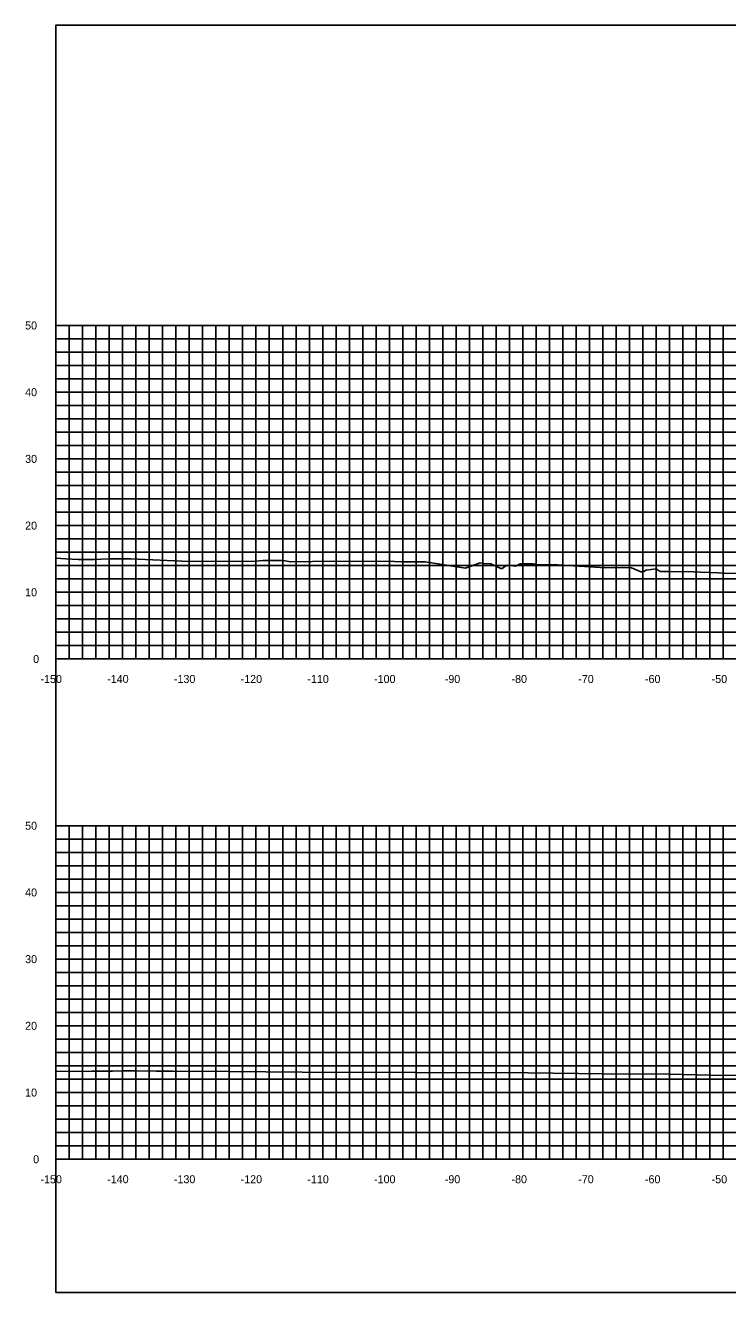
# Model space of a CAD drawing. Extents: x 1797714 to 1804825, y 249015 to 250269.
# Drawn here: x 1802109.6 to 1802214.9, y 249628.2 to 249818.2 of the extents above; entities that cross this region are included whole.
import ezdxf

# ---------------------------------------------------------------- set-up
doc = ezdxf.new("R2010")
doc.units = 0
for name, color, linetype in [('10', 7, 'Continuous'), ('31', 7, 'Continuous'), ('60', 7, 'Continuous'), ('Level 62', 7, 'Continuous'), ('M-ROADS', 7, 'Continuous')]:
    doc.layers.add(name, color=color, linetype=linetype)

msp = doc.modelspace()

# ---------------------------------------------------------------- linework, layer by layer
msp.add_lwpolyline([(1802114.16, 249628.17), (1802414.16, 249628.17), (1802414.16, 249818.17), (1802114.16, 249818.17)], close=True)
at = {"layer": '60'}
for p, q in [((1802114.1, 249773.17), (1802114.16, 249773.17)), ((1802114.16, 249723.17), (1802114.16, 249773.17)), ((1802114.1, 249763.17), (1802114.16, 249763.17)), ((1802114.1, 249753.17), (1802114.16, 249753.17)), ((1802114.1, 249743.17), (1802114.16, 249743.17)), ((1802114.1, 249733.17), (1802114.16, 249733.17)), ((1802114.1, 249723.17), (1802114.16, 249723.17)), ((1802114.16, 249723.17), (1802414.16, 249723.17)), ((1802114.16, 249723.11), (1802114.16, 249723.17)), ((1802124.16, 249723.11), (1802124.16, 249723.17)), ((1802134.16, 249723.11), (1802134.16, 249723.17)), ((1802144.16, 249723.11), (1802144.16, 249723.17)), ((1802154.16, 249723.11), (1802154.16, 249723.17)), ((1802164.16, 249723.11), (1802164.16, 249723.17)), ((1802174.16, 249723.11), (1802174.16, 249723.17)), ((1802184.16, 249723.11), (1802184.16, 249723.17)), ((1802194.16, 249723.11), (1802194.16, 249723.17)), ((1802204.16, 249723.11), (1802204.16, 249723.17)), ((1802214.16, 249723.11), (1802214.16, 249723.17)), ((1802114.1, 249698.17), (1802114.16, 249698.17)), ((1802114.16, 249648.17), (1802114.16, 249698.17)), ((1802114.1, 249688.17), (1802114.16, 249688.17)), ((1802114.1, 249678.17), (1802114.16, 249678.17)), ((1802114.1, 249668.17), (1802114.16, 249668.17)), ((1802114.1, 249658.17), (1802114.16, 249658.17)), ((1802114.1, 249648.17), (1802114.16, 249648.17)), ((1802114.16, 249648.17), (1802414.16, 249648.17)), ((1802114.16, 249648.11), (1802114.16, 249648.17)), ((1802124.16, 249648.11), (1802124.16, 249648.17)), ((1802134.16, 249648.11), (1802134.16, 249648.17)), ((1802144.16, 249648.11), (1802144.16, 249648.17)), ((1802154.16, 249648.11), (1802154.16, 249648.17)), ((1802164.16, 249648.11), (1802164.16, 249648.17)), ((1802174.16, 249648.11), (1802174.16, 249648.17)), ((1802184.16, 249648.11), (1802184.16, 249648.17)), ((1802194.16, 249648.11), (1802194.16, 249648.17)), ((1802204.16, 249648.11), (1802204.16, 249648.17)), ((1802214.16, 249648.11), (1802214.16, 249648.17))]:
    msp.add_line(p, q, dxfattribs=at)
at = {"layer": 'Level 62'}
for p, q in [((1802114.16, 249773.17), (1802414.16, 249773.17)), ((1802114.16, 249723.17), (1802114.16, 249773.17)), ((1802116.16, 249723.17), (1802116.16, 249773.17)), ((1802118.16, 249723.17), (1802118.16, 249773.17)), ((1802120.16, 249723.17), (1802120.16, 249773.17)), ((1802122.16, 249723.17), (1802122.16, 249773.17)), ((1802124.16, 249723.17), (1802124.16, 249773.17)), ((1802126.16, 249723.17), (1802126.16, 249773.17)), ((1802128.16, 249723.17), (1802128.16, 249773.17)), ((1802130.16, 249723.17), (1802130.16, 249773.17)), ((1802132.16, 249723.17), (1802132.16, 249773.17)), ((1802134.16, 249723.17), (1802134.16, 249773.17)), ((1802136.16, 249723.17), (1802136.16, 249773.17)), ((1802138.16, 249723.17), (1802138.16, 249773.17)), ((1802140.16, 249723.17), (1802140.16, 249773.17)), ((1802142.16, 249723.17), (1802142.16, 249773.17)), ((1802144.16, 249723.17), (1802144.16, 249773.17)), ((1802146.16, 249723.17), (1802146.16, 249773.17)), ((1802148.16, 249723.17), (1802148.16, 249773.17)), ((1802150.16, 249723.17), (1802150.16, 249773.17)), ((1802152.16, 249723.17), (1802152.16, 249773.17)), ((1802154.16, 249723.17), (1802154.16, 249773.17)), ((1802156.16, 249723.17), (1802156.16, 249773.17)), ((1802158.16, 249723.17), (1802158.16, 249773.17)), ((1802160.16, 249723.17), (1802160.16, 249773.17)), ((1802162.16, 249723.17), (1802162.16, 249773.17)), ((1802164.16, 249723.17), (1802164.16, 249773.17)), ((1802166.16, 249723.17), (1802166.16, 249773.17)), ((1802168.16, 249723.17), (1802168.16, 249773.17)), ((1802170.16, 249723.17), (1802170.16, 249773.17)), ((1802172.16, 249723.17), (1802172.16, 249773.17)), ((1802174.16, 249723.17), (1802174.16, 249773.17)), ((1802176.16, 249723.17), (1802176.16, 249773.17)), ((1802178.16, 249723.17), (1802178.16, 249773.17)), ((1802180.16, 249723.17), (1802180.16, 249773.17)), ((1802182.16, 249723.17), (1802182.16, 249773.17)), ((1802184.16, 249723.17), (1802184.16, 249773.17)), ((1802186.16, 249723.17), (1802186.16, 249773.17)), ((1802188.16, 249723.17), (1802188.16, 249773.17)), ((1802190.16, 249723.17), (1802190.16, 249773.17)), ((1802192.16, 249723.17), (1802192.16, 249773.17)), ((1802194.16, 249723.17), (1802194.16, 249773.17)), ((1802196.16, 249723.17), (1802196.16, 249773.17)), ((1802198.16, 249723.17), (1802198.16, 249773.17)), ((1802200.16, 249723.17), (1802200.16, 249773.17)), ((1802202.16, 249723.17), (1802202.16, 249773.17)), ((1802204.16, 249723.17), (1802204.16, 249773.17)), ((1802206.16, 249723.17), (1802206.16, 249773.17)), ((1802208.16, 249723.17), (1802208.16, 249773.17)), ((1802210.16, 249723.17), (1802210.16, 249773.17)), ((1802212.16, 249723.17), (1802212.16, 249773.17)), ((1802214.16, 249723.17), (1802214.16, 249773.17)), ((1802114.16, 249771.17), (1802414.16, 249771.17)), ((1802114.16, 249769.17), (1802414.16, 249769.17)), ((1802114.16, 249767.17), (1802414.16, 249767.17)), ((1802114.16, 249765.17), (1802414.16, 249765.17)), ((1802114.16, 249763.17), (1802414.16, 249763.17)), ((1802114.16, 249761.17), (1802414.16, 249761.17)), ((1802114.16, 249759.17), (1802414.16, 249759.17)), ((1802114.16, 249757.17), (1802414.16, 249757.17)), ((1802114.16, 249755.17), (1802414.16, 249755.17)), ((1802114.16, 249753.17), (1802414.16, 249753.17)), ((1802114.16, 249751.17), (1802414.16, 249751.17)), ((1802114.16, 249749.17), (1802414.16, 249749.17)), ((1802114.16, 249747.17), (1802414.16, 249747.17)), ((1802114.16, 249745.17), (1802414.16, 249745.17)), ((1802114.16, 249743.17), (1802414.16, 249743.17)), ((1802114.16, 249741.17), (1802414.16, 249741.17)), ((1802114.16, 249739.17), (1802414.16, 249739.17)), ((1802114.16, 249737.17), (1802414.16, 249737.17)), ((1802114.16, 249735.17), (1802414.16, 249735.17)), ((1802114.16, 249733.17), (1802414.16, 249733.17)), ((1802114.16, 249731.17), (1802414.16, 249731.17)), ((1802114.16, 249729.17), (1802414.16, 249729.17)), ((1802114.16, 249727.17), (1802414.16, 249727.17)), ((1802114.16, 249725.17), (1802414.16, 249725.17)), ((1802114.16, 249723.17), (1802414.16, 249723.17)), ((1802114.16, 249698.17), (1802414.16, 249698.17)), ((1802114.16, 249648.17), (1802114.16, 249698.17)), ((1802116.16, 249648.17), (1802116.16, 249698.17)), ((1802118.16, 249648.17), (1802118.16, 249698.17)), ((1802120.16, 249648.17), (1802120.16, 249698.17)), ((1802122.16, 249648.17), (1802122.16, 249698.17)), ((1802124.16, 249648.17), (1802124.16, 249698.17)), ((1802126.16, 249648.17), (1802126.16, 249698.17)), ((1802128.16, 249648.17), (1802128.16, 249698.17)), ((1802130.16, 249648.17), (1802130.16, 249698.17)), ((1802132.16, 249648.17), (1802132.16, 249698.17)), ((1802134.16, 249648.17), (1802134.16, 249698.17)), ((1802136.16, 249648.17), (1802136.16, 249698.17)), ((1802138.16, 249648.17), (1802138.16, 249698.17)), ((1802140.16, 249648.17), (1802140.16, 249698.17)), ((1802142.16, 249648.17), (1802142.16, 249698.17)), ((1802144.16, 249648.17), (1802144.16, 249698.17)), ((1802146.16, 249648.17), (1802146.16, 249698.17)), ((1802148.16, 249648.17), (1802148.16, 249698.17)), ((1802150.16, 249648.17), (1802150.16, 249698.17)), ((1802152.16, 249648.17), (1802152.16, 249698.17)), ((1802154.16, 249648.17), (1802154.16, 249698.17)), ((1802156.16, 249648.17), (1802156.16, 249698.17)), ((1802158.16, 249648.17), (1802158.16, 249698.17)), ((1802160.16, 249648.17), (1802160.16, 249698.17)), ((1802162.16, 249648.17), (1802162.16, 249698.17)), ((1802164.16, 249648.17), (1802164.16, 249698.17)), ((1802166.16, 249648.17), (1802166.16, 249698.17)), ((1802168.16, 249648.17), (1802168.16, 249698.17)), ((1802170.16, 249648.17), (1802170.16, 249698.17)), ((1802172.16, 249648.17), (1802172.16, 249698.17)), ((1802174.16, 249648.17), (1802174.16, 249698.17)), ((1802176.16, 249648.17), (1802176.16, 249698.17)), ((1802178.16, 249648.17), (1802178.16, 249698.17)), ((1802180.16, 249648.17), (1802180.16, 249698.17)), ((1802182.16, 249648.17), (1802182.16, 249698.17)), ((1802184.16, 249648.17), (1802184.16, 249698.17)), ((1802186.16, 249648.17), (1802186.16, 249698.17)), ((1802188.16, 249648.17), (1802188.16, 249698.17)), ((1802190.16, 249648.17), (1802190.16, 249698.17)), ((1802192.16, 249648.17), (1802192.16, 249698.17)), ((1802194.16, 249648.17), (1802194.16, 249698.17)), ((1802196.16, 249648.17), (1802196.16, 249698.17)), ((1802198.16, 249648.17), (1802198.16, 249698.17)), ((1802200.16, 249648.17), (1802200.16, 249698.17)), ((1802202.16, 249648.17), (1802202.16, 249698.17)), ((1802204.16, 249648.17), (1802204.16, 249698.17)), ((1802206.16, 249648.17), (1802206.16, 249698.17)), ((1802208.16, 249648.17), (1802208.16, 249698.17)), ((1802210.16, 249648.17), (1802210.16, 249698.17)), ((1802212.16, 249648.17), (1802212.16, 249698.17)), ((1802214.16, 249648.17), (1802214.16, 249698.17)), ((1802114.16, 249696.17), (1802414.16, 249696.17)), ((1802114.16, 249694.17), (1802414.16, 249694.17)), ((1802114.16, 249692.17), (1802414.16, 249692.17)), ((1802114.16, 249690.17), (1802414.16, 249690.17)), ((1802114.16, 249688.17), (1802414.16, 249688.17)), ((1802114.16, 249686.17), (1802414.16, 249686.17)), ((1802114.16, 249684.17), (1802414.16, 249684.17)), ((1802114.16, 249682.17), (1802414.16, 249682.17)), ((1802114.16, 249680.17), (1802414.16, 249680.17)), ((1802114.16, 249678.17), (1802414.16, 249678.17)), ((1802114.16, 249676.17), (1802414.16, 249676.17)), ((1802114.16, 249674.17), (1802414.16, 249674.17)), ((1802114.16, 249672.17), (1802414.16, 249672.17)), ((1802114.16, 249670.17), (1802414.16, 249670.17)), ((1802114.16, 249668.17), (1802414.16, 249668.17)), ((1802114.16, 249666.17), (1802414.16, 249666.17)), ((1802114.16, 249664.17), (1802414.16, 249664.17)), ((1802114.16, 249662.17), (1802414.16, 249662.17)), ((1802114.16, 249660.17), (1802414.16, 249660.17)), ((1802114.16, 249658.17), (1802414.16, 249658.17)), ((1802114.16, 249656.17), (1802414.16, 249656.17)), ((1802114.16, 249654.17), (1802414.16, 249654.17)), ((1802114.16, 249652.17), (1802414.16, 249652.17)), ((1802114.16, 249650.17), (1802414.16, 249650.17)), ((1802114.16, 249648.17), (1802414.16, 249648.17))]:
    msp.add_line(p, q, dxfattribs=at)
at = {"layer": 'M-ROADS'}
for points in [[(1802114.16, 249738.28), (1802115.64, 249738.19), (1802117.53, 249738.08), (1802119.91, 249738.08), (1802122.14, 249738.17), (1802125.39, 249738.2), (1802134.16, 249737.78), (1802144.05, 249737.84), (1802145.19, 249737.94), (1802146.92, 249737.94), (1802148.22, 249737.94), (1802149.37, 249737.71), (1802155.85, 249737.85), (1802164.91, 249737.76), (1802165.98, 249737.74), (1802166.87, 249737.74), (1802168.07, 249737.74), (1802169.51, 249737.75), (1802175.56, 249736.79), (1802175.68, 249736.82), (1802177.74, 249737.58), (1802178.3, 249737.5), (1802179.34, 249737.45), (1802180.87, 249736.75), (1802181.11, 249736.72), (1802181.18, 249736.83), (1802181.81, 249737.22), (1802183.07, 249737.08), (1802183.75, 249737.45), (1802183.79, 249737.44), (1802183.94, 249737.45), (1802185.71, 249737.42), (1802186.53, 249737.28), (1802189.01, 249737.28), (1802189.08, 249737.28), (1802189.33, 249737.27), (1802196.61, 249736.82), (1802199.03, 249736.89), (1802200.42, 249736.82), (1802201.85, 249736.23), (1802202.18, 249736.22), (1802202.62, 249736.49), (1802204.13, 249736.67), (1802204.76, 249736.28), (1802206.11, 249736.3), (1802209.76, 249736.26), (1802210.76, 249736.2), (1802213.46, 249736.08), (1802214.35, 249736.06), (1802216.33, 249736.01)], [(1802114.16, 249661.34), (1802119.55, 249661.35), (1802122.67, 249661.37), (1802124.18, 249661.42), (1802125.6, 249661.41), (1802126.01, 249661.42), (1802126.16, 249661.41), (1802126.22, 249661.41), (1802129.25, 249661.39), (1802131.72, 249661.39), (1802140.2, 249661.34), (1802151.06, 249661.22), (1802184.94, 249661.11), (1802196.27, 249660.97), (1802200.84, 249660.92), (1802204.19, 249660.95), (1802212.33, 249660.77), (1802216.44, 249660.72)]]:
    msp.add_lwpolyline(points, dxfattribs=at)

# ---------------------------------------------------------------- texts
at = {"layer": '10'}
for s, p in [('-150', (1802111.86, 249719.57)), ('-140', (1802121.86, 249719.57)), ('-130', (1802131.86, 249719.57)), ('-120', (1802141.86, 249719.57)), ('-110', (1802151.86, 249719.57)), ('-100', (1802161.86, 249719.57)), ('-90', (1802172.46, 249719.57)), ('-80', (1802182.46, 249719.57)), ('-70', (1802192.46, 249719.57)), ('-60', (1802202.46, 249719.57)), ('-50', (1802212.46, 249719.57)), ('-150', (1802111.86, 249644.57)), ('-140', (1802121.86, 249644.57)), ('-130', (1802131.86, 249644.57)), ('-120', (1802141.86, 249644.57)), ('-110', (1802151.86, 249644.57)), ('-100', (1802161.86, 249644.57)), ('-90', (1802172.46, 249644.57)), ('-80', (1802182.46, 249644.57)), ('-70', (1802192.46, 249644.57)), ('-60', (1802202.46, 249644.57)), ('-50', (1802212.46, 249644.57))]:
    msp.add_text(s, height=1.2, dxfattribs=at).set_placement(p)
at = {"layer": '31'}
for s, p in [('50', (1802109.56, 249772.57)), ('40', (1802109.56, 249762.57)), ('30', (1802109.56, 249752.57)), ('20', (1802109.56, 249742.57)), ('10', (1802109.56, 249732.57)), ('0', (1802110.76, 249722.57)), ('50', (1802109.56, 249697.57)), ('40', (1802109.56, 249687.57)), ('30', (1802109.56, 249677.57)), ('20', (1802109.56, 249667.57)), ('10', (1802109.56, 249657.57)), ('0', (1802110.76, 249647.57))]:
    msp.add_text(s, height=1.2, dxfattribs=at).set_placement(p)
at = {"layer": '60'}
for p in [(1802114.16, 249723.17), (1802114.16, 249648.17)]:
    msp.add_text('-', height=0.0001, dxfattribs=at).set_placement(p)

doc.saveas('drawing.dxf')
